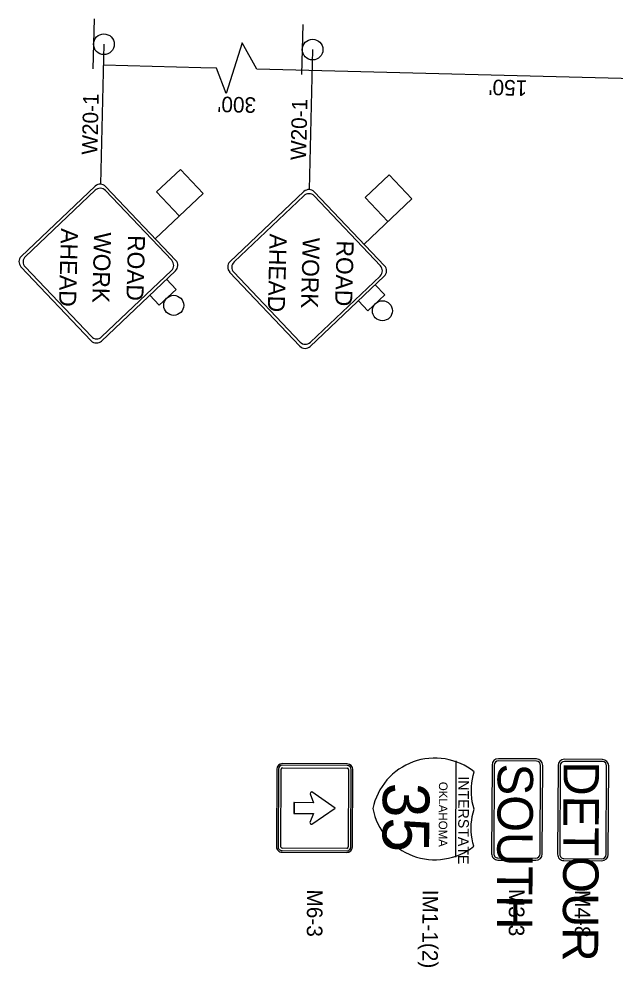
# Model space of a CAD drawing. Extents: x 2135767 to 2151731, y 141839 to 175894.
# Drawn here: x 2150208.9 to 2150438.8, y 145248.5 to 145614.3 of the extents above; entities that cross this region are included whole.
import ezdxf

# ---------------------------------------------------------------- set-up
doc = ezdxf.new("R2010")
doc.units = 0
for name, color, linetype in [('PR_Dimensions_Phase1', 7, 'Continuous'), ('PR_Phasing_Detour_1', 7, 'Continuous'), ('PR_Phasing_Traffic_Control_Devices_1', 7, 'Continuous'), ('PR_Txt', 7, 'Continuous'), ('PR_Txt_Phase_1', 7, 'Continuous')]:
    doc.layers.add(name, color=color, linetype=linetype)

# ---------------------------------------------------------------- blocks, each defined once
blk = doc.blocks.new('FLSHFLAG')
at = {"layer": 'PR_Txt'}
for p, q in [((-1.202, 14.125), (0.838, 16.147)), ((0.838, 16.147), (4.9, 12.085)), ((0.819, 12.085), (-1.202, 14.125)), ((0.819, 12.085), (2.86, 14.106)), ((9.258, 14.004), (8.403, 13.149)), ((9.258, 14.004), (10.685, 12.576)), ((10.685, 12.576), (9.831, 11.722))]:
    blk.add_line(p, q, dxfattribs=at)
blk.add_circle((10.653, 13.836), 0.873, dxfattribs=at)

msp = doc.modelspace()

# ---------------------------------------------------------------- linework, layer by layer
at = {"layer": 'PR_Dimensions_Phase1'}
for p, q in [((2150241.63, 145604.53), (2150240.29, 145550.55)), ((2150322.15, 145602.45), (2150320.82, 145548.46))]:
    msp.add_line(p, q, dxfattribs=at)
msp.add_lwpolyline([(2150621.85, 145586.62), (2150300.64, 145594.91), (2150294.97, 145605.06), (2150288.79, 145585.47), (2150285.1, 145595.31), (2150279.06, 145595.47), (2150241.43, 145596.44)], dxfattribs=at)
at = {"layer": 'PR_Phasing_Detour_1'}
for p, q in [((2150377.47, 145328.05), (2150377.28, 145290.86)), ((2150408.49, 145328.77), (2150393.84, 145328.85)), ((2150408.49, 145327.95), (2150393.84, 145328.03)), ((2150433.95, 145327.75), (2150419.29, 145327.82)), ((2150433.95, 145328.56), (2150419.3, 145328.64)), ((2150308.35, 145324.83), (2150308.2, 145294.97)), ((2150308.96, 145324.83), (2150308.81, 145294.97)), ((2150308.96, 145324.83), (2150308.81, 145294.97)), ((2150309.83, 145294.96), (2150309.98, 145324.82)), ((2150309.83, 145294.96), (2150309.98, 145324.82)), ((2150310.52, 145325.36), (2150335.5, 145325.23)), ((2150310.52, 145325.35), (2150335.5, 145325.22)), ((2150335.51, 145326.85), (2150310.53, 145326.98)), ((2150335.5, 145326.24), (2150310.53, 145326.37)), ((2150335.5, 145326.24), (2150310.53, 145326.37)), ((2150336.03, 145324.69), (2150335.87, 145294.83)), ((2150336.03, 145324.69), (2150335.87, 145294.83)), ((2150336.89, 145294.82), (2150337.05, 145324.68)), ((2150336.89, 145294.82), (2150337.05, 145324.68)), ((2150337.5, 145294.82), (2150337.66, 145324.68)), ((2150391.39, 145326.42), (2150391.21, 145292.23)), ((2150392.2, 145326.41), (2150392.02, 145292.22)), ((2150409.93, 145292.13), (2150410.11, 145326.32)), ((2150410.75, 145292.13), (2150410.92, 145326.31)), ((2150416.84, 145326.21), (2150416.67, 145292.02)), ((2150417.66, 145326.21), (2150417.48, 145292.02)), ((2150435.39, 145291.92), (2150435.57, 145326.11)), ((2150436.2, 145291.92), (2150436.38, 145326.11)), ((2150321.18, 145315.38), (2150322.55, 145311.91)), ((2150330.86, 145309.78), (2150321.88, 145316.07)), ((2150315, 145311.95), (2150314.98, 145307.78)), ((2150322.55, 145311.91), (2150315, 145311.95)), ((2150321.81, 145303.59), (2150330.86, 145309.78)), ((2150314.98, 145307.78), (2150322.53, 145307.75)), ((2150322.53, 145307.75), (2150321.12, 145304.28)), ((2150310.35, 145292.8), (2150335.33, 145292.67)), ((2150335.34, 145294.29), (2150310.36, 145294.42)), ((2150335.34, 145294.29), (2150310.36, 145294.42)), ((2150310.36, 145293.41), (2150335.33, 145293.28)), ((2150310.36, 145293.41), (2150335.33, 145293.28)), ((2150393.64, 145290.59), (2150408.3, 145290.51)), ((2150393.64, 145289.77), (2150408.29, 145289.7)), ((2150419.09, 145289.57), (2150433.75, 145289.49)), ((2150419.1, 145290.38), (2150433.75, 145290.31))]:
    msp.add_line(p, q, dxfattribs=at)
for points in [[(2150384.52, 145323.78), (2150383.27, 145324.72), (2150381.97, 145325.57), (2150380.61, 145326.33), (2150379.21, 145327.01), (2150377.77, 145327.6), (2150376.29, 145328.09), (2150374.79, 145328.49), (2150373.26, 145328.79), (2150371.71, 145329), (2150370.16, 145329.1), (2150368.6, 145329.11), (2150367.05, 145329.01), (2150365.5, 145328.82), (2150363.97, 145328.53), (2150362.47, 145328.14), (2150360.99, 145327.66), (2150359.54, 145327.09), (2150358.13, 145326.42), (2150356.77, 145325.66), (2150355.46, 145324.82), (2150354.21, 145323.9), (2150353.01, 145322.9), (2150351.89, 145321.83), (2150350.83, 145320.68), (2150349.85, 145319.47), (2150348.95, 145318.21), (2150348.13, 145316.88), (2150347.39, 145315.51), (2150346.75, 145314.09), (2150346.19, 145312.64), (2150345.74, 145311.15), (2150345.37, 145309.63), (2150345.72, 145308.12), (2150346.16, 145306.62), (2150346.7, 145305.16), (2150347.33, 145303.74), (2150348.05, 145302.36), (2150348.86, 145301.03), (2150349.74, 145299.75), (2150350.71, 145298.53), (2150351.76, 145297.37), (2150352.87, 145296.29), (2150354.06, 145295.28), (2150355.3, 145294.34), (2150356.6, 145293.49), (2150357.96, 145292.72), (2150359.36, 145292.04), (2150360.8, 145291.44), (2150362.27, 145290.95), (2150363.78, 145290.54), (2150365.3, 145290.24), (2150366.85, 145290.03), (2150368.4, 145289.92), (2150369.96, 145289.91), (2150371.51, 145290), (2150373.06, 145290.19), (2150374.59, 145290.47), (2150376.1, 145290.86), (2150377.58, 145291.34), (2150379.03, 145291.91), (2150380.44, 145292.57), (2150381.8, 145293.32), (2150383.11, 145294.16), (2150384.37, 145295.08), (2150383.99, 145296.48), (2150383.7, 145297.91), (2150383.49, 145299.35), (2150383.36, 145300.8), (2150383.33, 145302.26), (2150383.38, 145303.72), (2150383.52, 145305.17), (2150383.74, 145306.6), (2150384.05, 145308.03), (2150384.44, 145309.43), (2150384.07, 145310.84), (2150383.77, 145312.26), (2150383.56, 145313.71), (2150383.44, 145315.16), (2150383.4, 145316.61), (2150383.45, 145318.07), (2150383.59, 145319.52), (2150383.82, 145320.96), (2150384.13, 145322.38), (2150384.52, 145323.78)], [(2150321.15, 145315.38), (2150322.52, 145311.91), (2150314.97, 145311.95), (2150314.95, 145307.78), (2150322.5, 145307.74), (2150321.1, 145304.28)], [(2150330.84, 145309.78), (2150321.85, 145316.07)], [(2150321.79, 145303.59), (2150330.84, 145309.78)]]:
    msp.add_lwpolyline(points, dxfattribs=at)
for centre, radius, start, end in [((2150393.83, 145326.4), 2.44, 89.7019, 179.7019), ((2150393.83, 145326.4), 1.63, 89.7019, 179.7019), ((2150408.48, 145326.33), 2.44, 359.7019, 89.7019), ((2150408.48, 145326.33), 1.63, 359.7019, 89.7019), ((2150419.29, 145326.2), 2.44, 89.7019, 179.7019), ((2150419.29, 145326.2), 1.63, 89.7019, 179.7019), ((2150433.94, 145326.12), 2.44, 359.7019, 89.7019), ((2150433.94, 145326.12), 1.63, 359.7019, 89.7019), ((2150310.52, 145324.82), 2.16, 89.7019, 179.7019), ((2150310.52, 145324.82), 1.55, 89.7019, 179.7019), ((2150310.52, 145324.82), 1.55, 89.7019, 179.7019), ((2150310.52, 145324.82), 0.537, 89.7019, 179.7019), ((2150310.52, 145324.82), 0.537, 89.7019, 179.7019), ((2150335.49, 145324.69), 1.55, 359.7019, 89.7019), ((2150335.49, 145324.69), 1.55, 359.7019, 89.7019), ((2150335.49, 145324.69), 0.537, 359.7019, 89.7019), ((2150335.49, 145324.69), 0.537, 359.7019, 89.7019), ((2150335.49, 145324.69), 2.16, 359.7019, 89.7019), ((2150321.85, 145315.38), 0.694, 89.7019, 179.7019), ((2150321.87, 145315.38), 0.694, 89.7019, 179.7019), ((2150321.79, 145304.28), 0.694, 179.7019, 269.7019), ((2150321.82, 145304.28), 0.694, 179.7019, 269.7019), ((2150310.36, 145294.96), 2.16, 179.7019, 269.7019), ((2150310.36, 145294.96), 1.55, 179.7019, 269.7019), ((2150310.36, 145294.96), 1.55, 179.7019, 269.7019), ((2150310.36, 145294.96), 0.537, 179.7019, 269.7019), ((2150310.36, 145294.96), 0.537, 179.7019, 269.7019), ((2150335.34, 145294.83), 2.16, 269.7019, 359.7019), ((2150335.34, 145294.83), 1.55, 269.7019, 359.7019), ((2150335.34, 145294.83), 1.55, 269.7019, 359.7019), ((2150335.34, 145294.83), 0.537, 269.7019, 359.7019), ((2150335.34, 145294.83), 0.537, 269.7019, 359.7019), ((2150393.65, 145292.22), 2.44, 179.7019, 269.7019), ((2150393.65, 145292.22), 1.63, 179.7019, 269.7019), ((2150408.3, 145292.14), 2.44, 269.7019, 359.7019), ((2150408.3, 145292.14), 1.63, 269.7019, 359.7019), ((2150419.11, 145292.01), 2.44, 179.7019, 269.7019), ((2150419.11, 145292.01), 1.63, 179.7019, 269.7019), ((2150433.76, 145291.93), 2.44, 269.7019, 359.7019), ((2150433.76, 145291.93), 1.63, 269.7019, 359.7019)]:
    msp.add_arc(centre, radius, start, end, dxfattribs=at)
at = {"layer": 'PR_Phasing_Traffic_Control_Devices_1'}
for p, q in [((2150237.87, 145614.28), (2150237.63, 145604.63)), ((2150318.39, 145612.19), (2150318.15, 145602.54)), ((2150237.63, 145604.63), (2150237.39, 145594.98)), ((2150318.15, 145602.54), (2150317.91, 145592.9)), ((2150238.28, 145549.77), (2150209.73, 145522.66)), ((2150238.24, 145548.18), (2150211.32, 145522.62)), ((2150267.78, 145521.16), (2150242.22, 145548.08)), ((2150269.37, 145521.12), (2150242.26, 145549.67)), ((2150318.81, 145547.69), (2150290.25, 145520.58)), ((2150349.9, 145519.04), (2150322.78, 145547.59)), ((2150318.76, 145546.1), (2150291.84, 145520.53)), ((2150348.31, 145519.08), (2150322.74, 145546)), ((2150209.63, 145518.68), (2150236.74, 145490.13)), ((2150211.22, 145518.64), (2150236.79, 145491.72)), ((2150240.72, 145490.03), (2150269.27, 145517.14)), ((2150240.76, 145491.62), (2150267.68, 145517.18)), ((2150290.15, 145516.6), (2150317.27, 145488.05)), ((2150291.74, 145516.56), (2150317.31, 145489.64)), ((2150321.24, 145487.95), (2150349.79, 145515.06)), ((2150321.28, 145489.54), (2150348.2, 145515.1))]:
    msp.add_line(p, q, dxfattribs=at)
for centre in [(2150241.63, 145604.53), (2150322.15, 145602.45)]:
    msp.add_circle(centre, 4, dxfattribs=at)
for centre, start, end in [((2150240.18, 145546.14), 43.5212, 133.5212), ((2150240.22, 145547.73), 43.5212, 133.5212), ((2150320.74, 145545.65), 43.5212, 133.5212), ((2150320.7, 145544.06), 43.5212, 133.5212), ((2150211.67, 145520.62), 133.5212, 223.5212), ((2150213.26, 145520.58), 133.5212, 223.5212), ((2150265.74, 145519.22), 313.5212, 43.5212), ((2150267.34, 145519.18), 313.5212, 43.5212), ((2150292.19, 145518.54), 133.5212, 223.5212), ((2150293.78, 145518.49), 133.5212, 223.5212), ((2150346.27, 145517.14), 313.5212, 43.5212), ((2150347.86, 145517.1), 313.5212, 43.5212), ((2150238.78, 145492.07), 223.5212, 313.5212), ((2150238.82, 145493.66), 223.5212, 313.5212), ((2150319.35, 145491.57), 223.5212, 313.5212), ((2150319.31, 145489.98), 223.5212, 313.5212)]:
    msp.add_arc(centre, 2.81, start, end, dxfattribs=at)

# ---------------------------------------------------------------- block references
at = {"layer": 'PR_Phasing_Traffic_Control_Devices_1', "xscale": 4.4291250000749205, "yscale": 4.42912500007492, "rotation": -91.47881942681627}
for p in [(2150208.52, 145552.54), (2150289.04, 145550.45)]:
    msp.add_blockref('FLSHFLAG', p, dxfattribs=at)

# ---------------------------------------------------------------- texts
at = {"layer": 'PR_Phasing_Detour_1'}
for s, height, p in [('SOUTH', 13.675, (2150393.56, 145327.04)), ('DETOUR', 13.675, (2150419.02, 145327.87)), ('INTERSTATE', 4.084, (2150378.43, 145322.09)), ('35', 17.974, (2150349.26, 145319.65)), ('OKLAHOMA', 3.31, (2150370.9, 145319.96)), ('M6-3', 6, (2150320.01, 145278.45)), ('IM1-1(2)', 6, (2150364.6, 145278.34)), ('M3-3', 6, (2150397.91, 145278.67)), ('M4-8', 6, (2150423.36, 145278.21))]:
    msp.add_text(s, height=height, rotation=269.7019, dxfattribs=at).set_placement(p)
at = {"layer": 'PR_Phasing_Traffic_Control_Devices_1'}
for s, p in [('AHEAD', (2150225.09, 145533.56)), ('WORK', (2150237.86, 145532.07)), ('ROAD', (2150250.96, 145530.94)), ('AHEAD', (2150305.62, 145531.47)), ('WORK', (2150318.38, 145529.98)), ('ROAD', (2150331.48, 145528.86))]:
    msp.add_text(s, height=6.562, rotation=268.5212, dxfattribs=at).set_placement(p)
at = {"layer": 'PR_Txt_Phase_1'}
for s, rotation, p in [("150'", 178.5212, (2150405.04, 145590.55)), ('W20-1', 88.5859, (2150239.09, 145561.84)), ("300'", 178.5212, (2150300.43, 145584)), ('W20-1', 88.5859, (2150319.61, 145559.76))]:
    msp.add_text(s, height=6, rotation=rotation, dxfattribs=at).set_placement(p)

doc.saveas('drawing.dxf')
